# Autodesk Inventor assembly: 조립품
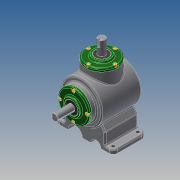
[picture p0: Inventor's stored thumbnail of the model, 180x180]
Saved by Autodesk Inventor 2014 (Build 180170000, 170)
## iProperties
Created: 2018-08
Part Number: 조립품
Document SubType Name: Assembly
Designer: kb542
Author: kb542
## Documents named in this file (14)
- C:\Users\kb542\Desktop\480807V1028\조립품.iam
- C:\Users\kb542\Desktop\480807V1028\본체.ipt
- C:\Users\kb542\Desktop\480807V1028\메인 축.ipt
- 메인 축.ipt
- C:\Users\kb542\Desktop\480807V1028\키 5x5.ipt
- C:\Users\kb542\Desktop\480807V1028\메인 베벨기어.ipt
- C:\Users\kb542\Desktop\480807V1028\베어링 6203.ipt
- C:\Users\kb542\Desktop\480807V1028\커버.ipt
- C:\Users\kb542\Desktop\480807V1028\오일실 17 32 8.ipt
- C:\Users\kb542\Desktop\480807V1028\볼트 M4.ipt
- C:\Users\kb542\Desktop\480807V1028\서브 축.ipt
- 서브 축.ipt
- C:\Users\kb542\Desktop\480807V1028\서브 베벨기어.ipt
- C:\Users\kb542\Desktop\480807V1028\키 4x4.ipt
